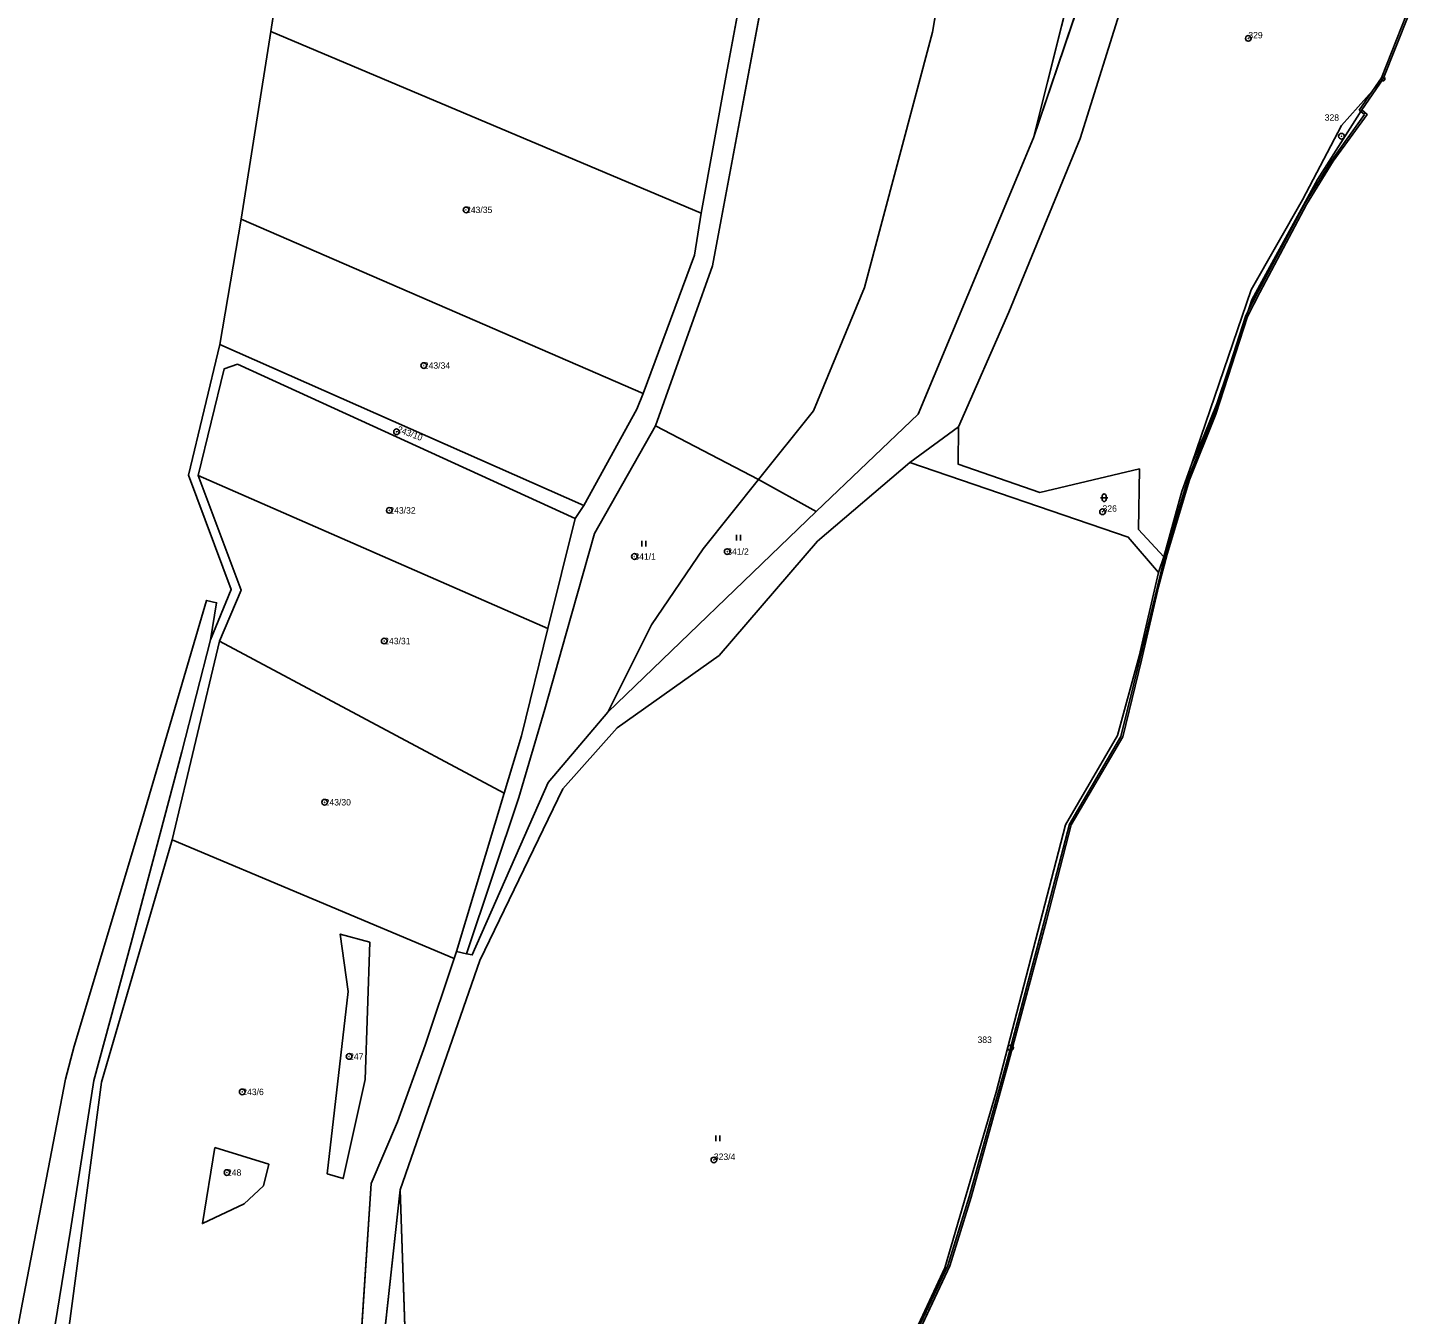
# Model space of a CAD drawing. Extents: x -652854 to -650068, y -1097661 to -1095417.
# Drawn here: x -650849.8 to -650484.7, y -1096839 to -1096498.9 of the extents above; entities that cross this region are included whole.
import ezdxf

# ---------------------------------------------------------------- set-up
doc = ezdxf.new("R2010")
doc.units = 0
for name, color, linetype in [('Definiční body parcel', 7, 'Continuous'), ('Geodetické body', 7, 'Continuous'), ('Hranice kat_ území', 7, 'Continuous'), ('Hranice parcel', 7, 'Continuous'), ('Obvody jako plochy', 7, 'Continuous'), ('Ostatní hranice', 7, 'Continuous'), ('Parcelní čísla', 7, 'Continuous'), ('Prvky pro prodl_ par_ č_', 7, 'Continuous'), ('Značky kultur', 7, 'Continuous')]:
    doc.layers.add(name, color=color, linetype=linetype)

msp = doc.modelspace()

# ---------------------------------------------------------------- linework, layer by layer
at = {"layer": 'Definiční body parcel'}
for centre, radius in [((-650526.99, -1096501.73), 0.75), ((-650526.99, -1096501.73), 0.0327), ((-650502.35, -1096527.6), 0.75), ((-650502.35, -1096527.6), 0.0327), ((-650733.87, -1096547.05), 0.75), ((-650733.87, -1096547.05), 0.0327), ((-650745.04, -1096588.2), 0.75), ((-650745.04, -1096588.2), 0.0327), ((-650752.26, -1096605.71), 0.75), ((-650752.26, -1096605.71), 0.0327), ((-650754.16, -1096626.49), 0.75), ((-650754.16, -1096626.49), 0.0327), ((-650565.55, -1096626.85), 0.75), ((-650565.55, -1096626.85), 0.0327), ((-650664.79, -1096637.39), 0.75), ((-650664.79, -1096637.39), 0.0327), ((-650689.35, -1096638.68), 0.75), ((-650689.35, -1096638.68), 0.0327), ((-650755.52, -1096661.03), 0.75), ((-650755.52, -1096661.03), 0.0327), ((-650771.27, -1096703.64), 0.75), ((-650771.27, -1096703.64), 0.0327), ((-650589.86, -1096768.59), 0.75), ((-650589.86, -1096768.59), 0.0327), ((-650764.8, -1096770.84), 0.75), ((-650764.8, -1096770.84), 0.0327), ((-650793.05, -1096780.2), 0.75), ((-650793.05, -1096780.2), 0.0327), ((-650668.33, -1096798.19), 0.75), ((-650668.33, -1096798.19), 0.0327), ((-650797.1, -1096801.52), 0.75), ((-650797.1, -1096801.52), 0.0327)]:
    msp.add_circle(centre, radius, dxfattribs=at)
at = {"layer": 'Geodetické body'}
for radius in [0.5, 0.001]:
    msp.add_circle((-650491.37, -1096512.46), radius, dxfattribs=at)
at = {"layer": 'Hranice kat_ území'}
for p, q in [((-650484.66, -1096495.59), (-650491.37, -1096512.46)), ((-650491.37, -1096512.46), (-650496.97, -1096520.6)), ((-650496.97, -1096520.6), (-650495.58, -1096521.81)), ((-650495.58, -1096521.81), (-650504.51, -1096534.18)), ((-650504.51, -1096534.18), (-650511.64, -1096545.63)), ((-650511.64, -1096545.63), (-650523.96, -1096568.9)), ((-650523.96, -1096568.9), (-650527.17, -1096575.2)), ((-650527.17, -1096575.2), (-650535.56, -1096601.1)), ((-650535.56, -1096601.1), (-650542.51, -1096618.41)), ((-650542.51, -1096618.41), (-650548.42, -1096638.04)), ((-650548.42, -1096638.04), (-650550.78, -1096646.66)), ((-650550.78, -1096646.66), (-650555.22, -1096666.07)), ((-650555.22, -1096666.07), (-650560.2, -1096686.39)), ((-650560.2, -1096686.39), (-650573.84, -1096709.65)), ((-650573.84, -1096709.65), (-650580.35, -1096734.9)), ((-650580.35, -1096734.9), (-650590.56, -1096773.04)), ((-650590.56, -1096773.04), (-650600.33, -1096808.06)), ((-650600.33, -1096808.06), (-650605.92, -1096826.18)), ((-650605.92, -1096826.18), (-650620.6, -1096857.32))]:
    msp.add_line(p, q, dxfattribs=at)
at = {"layer": 'Hranice parcel'}
for p, q in [((-650785.54, -1096499.95), (-650773.41, -1096422.59)), ((-650598.36, -1096429.24), (-650610.51, -1096500.05)), ((-650652.9, -1096477.63), (-650668.72, -1096561.85)), ((-650658.91, -1096478.22), (-650664.97, -1096511.01)), ((-650572.68, -1096483.75), (-650583.78, -1096528.02)), ((-650583.78, -1096528.02), (-650569.29, -1096485.13)), ((-650559.7, -1096490.72), (-650571.47, -1096528.21)), ((-650793.31, -1096549.53), (-650785.54, -1096499.95)), ((-650785.54, -1096499.95), (-650671.73, -1096547.95)), ((-650610.51, -1096500.05), (-650628.48, -1096567.58)), ((-650664.97, -1096511.01), (-650671.73, -1096547.95)), ((-650491.37, -1096512.46), (-650502.32, -1096524.73)), ((-650508.68, -1096539.04), (-650496.97, -1096520.6)), ((-650502.32, -1096524.73), (-650512.64, -1096544.42)), ((-650614.31, -1096601.07), (-650583.78, -1096528.02)), ((-650571.47, -1096528.21), (-650590.36, -1096574.12)), ((-650511.9, -1096544.81), (-650508.68, -1096539.04)), ((-650512.64, -1096544.42), (-650526.23, -1096568.21)), ((-650526.06, -1096570.86), (-650511.9, -1096544.81)), ((-650798.99, -1096582.65), (-650793.31, -1096549.53)), ((-650793.31, -1096549.53), (-650687.01, -1096595.59)), ((-650671.73, -1096547.95), (-650673.43, -1096559)), ((-650673.43, -1096559), (-650687.01, -1096595.59)), ((-650668.72, -1096561.85), (-650683.81, -1096604.11)), ((-650628.48, -1096567.58), (-650641.96, -1096600.14)), ((-650526.23, -1096568.21), (-650541.95, -1096614.11)), ((-650535.28, -1096598.37), (-650526.06, -1096570.86)), ((-650590.36, -1096574.12), (-650603.62, -1096604.37)), ((-650807.31, -1096617.17), (-650798.99, -1096582.65)), ((-650702.71, -1096625.17), (-650798.99, -1096582.65)), ((-650797.8, -1096589.04), (-650804.72, -1096617.23)), ((-650794.34, -1096587.83), (-650797.8, -1096589.04)), ((-650705.03, -1096628.63), (-650794.34, -1096587.83)), ((-650687.01, -1096595.59), (-650688.71, -1096599.72)), ((-650688.71, -1096599.72), (-650702.71, -1096625.17)), ((-650641.96, -1096600.14), (-650656.55, -1096618.34)), ((-650538.65, -1096606.62), (-650535.28, -1096598.37)), ((-650683.81, -1096604.11), (-650699.9, -1096632.64)), ((-650656.55, -1096618.34), (-650683.81, -1096604.11)), ((-650614.31, -1096601.07), (-650641.3, -1096626.82)), ((-650603.62, -1096604.37), (-650616.47, -1096613.8)), ((-650603.69, -1096614.28), (-650603.62, -1096604.37)), ((-650541.95, -1096614.11), (-650538.65, -1096606.62)), ((-650616.47, -1096613.8), (-650640.95, -1096634.64)), ((-650616.47, -1096613.8), (-650558.74, -1096633.54)), ((-650582.16, -1096621.77), (-650603.69, -1096614.28)), ((-650555.81, -1096615.55), (-650582.16, -1096621.77)), ((-650556, -1096631.51), (-650555.81, -1096615.55)), ((-650541.95, -1096614.11), (-650544.57, -1096621.47)), ((-650795.97, -1096647.36), (-650807.31, -1096617.17)), ((-650804.72, -1096617.23), (-650793.38, -1096647.55)), ((-650804.72, -1096617.23), (-650712.28, -1096657.74)), ((-650656.55, -1096618.34), (-650671.15, -1096636.66)), ((-650641.3, -1096626.82), (-650656.55, -1096618.34)), ((-650544.57, -1096621.47), (-650549.36, -1096638.74)), ((-650702.71, -1096625.17), (-650705.03, -1096628.63)), ((-650705.03, -1096628.63), (-650712.28, -1096657.74)), ((-650696.37, -1096679.84), (-650641.3, -1096626.82)), ((-650699.9, -1096632.64), (-650707.4, -1096659)), ((-650558.74, -1096633.54), (-650550.76, -1096642.89)), ((-650549.36, -1096638.74), (-650556, -1096631.51)), ((-650671.15, -1096636.66), (-650684.79, -1096656.72)), ((-650640.95, -1096634.64), (-650666.97, -1096664.83)), ((-650550.76, -1096642.89), (-650549.36, -1096638.74)), ((-650550.76, -1096642.89), (-650555.85, -1096665.06)), ((-650801.47, -1096660.7), (-650795.97, -1096647.36)), ((-650799.05, -1096661.1), (-650793.38, -1096647.55)), ((-650802.47, -1096650.3), (-650819.95, -1096709.68)), ((-650799.85, -1096650.9), (-650802.47, -1096650.3)), ((-650801.47, -1096660.7), (-650799.85, -1096650.9)), ((-650712.28, -1096657.74), (-650719.22, -1096686.09)), ((-650707.4, -1096659), (-650713.04, -1096679)), ((-650684.79, -1096656.72), (-650696.37, -1096679.84)), ((-650811.59, -1096713.59), (-650799.05, -1096661.1)), ((-650809.04, -1096690.29), (-650801.47, -1096660.7)), ((-650799.05, -1096661.1), (-650723.79, -1096701.28)), ((-650666.97, -1096664.83), (-650693.87, -1096683.97)), ((-650555.85, -1096665.06), (-650561.55, -1096686.01)), ((-650713.04, -1096679), (-650719.9, -1096702.42)), ((-650712.12, -1096698.4), (-650696.37, -1096679.84)), ((-650693.87, -1096683.97), (-650708.27, -1096700.08)), ((-650719.22, -1096686.09), (-650723.79, -1096701.28)), ((-650561.55, -1096686.01), (-650575.38, -1096709.57)), ((-650822.45, -1096740.82), (-650809.04, -1096690.29)), ((-650732.22, -1096743.98), (-650712.12, -1096698.4)), ((-650723.79, -1096701.28), (-650736.37, -1096743.07)), ((-650719.9, -1096702.42), (-650733.72, -1096743.7)), ((-650708.27, -1096700.08), (-650730.26, -1096745.43)), ((-650819.95, -1096709.68), (-650837.51, -1096768.15)), ((-650575.38, -1096709.57), (-650593.68, -1096780.27)), ((-650830.29, -1096777.64), (-650811.59, -1096713.59)), ((-650737, -1096744.96), (-650811.59, -1096713.59)), ((-650759.32, -1096740.66), (-650767.12, -1096738.47)), ((-650767.12, -1096738.47), (-650765.09, -1096753.67)), ((-650832.35, -1096777.19), (-650822.45, -1096740.82)), ((-650760.55, -1096776.92), (-650759.32, -1096740.66)), ((-650736.37, -1096743.07), (-650737, -1096744.96)), ((-650736.37, -1096743.07), (-650733.72, -1096743.7)), ((-650730.26, -1096745.43), (-650751.3, -1096806.09)), ((-650737, -1096744.96), (-650744.66, -1096767.85)), ((-650733.72, -1096743.7), (-650732.22, -1096743.98)), ((-650765.09, -1096753.67), (-650770.62, -1096801.88)), ((-650837.51, -1096768.15), (-650839.76, -1096776.84)), ((-650744.66, -1096767.85), (-650752, -1096788.15)), ((-650839.76, -1096776.84), (-650851.23, -1096836.35)), ((-650838.97, -1096843.48), (-650830.29, -1096777.64)), ((-650838.52, -1096816.73), (-650832.35, -1096777.19)), ((-650766.33, -1096803.11), (-650760.55, -1096776.92)), ((-650593.68, -1096780.27), (-650607.29, -1096826.73)), ((-650752, -1096788.15), (-650758.96, -1096804.4)), ((-650800.3, -1096794.9), (-650803.58, -1096815)), ((-650786.07, -1096799.32), (-650800.3, -1096794.9)), ((-650787.47, -1096805.01), (-650786.07, -1096799.32)), ((-650792.55, -1096809.79), (-650787.47, -1096805.01)), ((-650770.62, -1096801.88), (-650766.33, -1096803.11)), ((-650758.96, -1096804.4), (-650762.71, -1096861.22)), ((-650751.3, -1096806.09), (-650757.77, -1096864.86)), ((-650749.78, -1096850.04), (-650751.3, -1096806.09)), ((-650803.58, -1096815), (-650792.55, -1096809.79)), ((-650842.5, -1096841.66), (-650838.52, -1096816.73)), ((-650607.29, -1096826.73), (-650631.79, -1096879.39))]:
    msp.add_line(p, q, dxfattribs=at)
at = {"layer": 'Obvody jako plochy'}
for points in [[(-650615.39, -1096224.69), (-650627.74, -1096265.94), (-650633.03, -1096284.37), (-650678.51, -1096272.34), (-650676.87, -1096343.5), (-650663.97, -1096403.54), (-650652.67, -1096447.91), (-650652.9, -1096477.63), (-650668.72, -1096561.85), (-650683.81, -1096604.11), (-650656.55, -1096618.34), (-650641.96, -1096600.14), (-650628.48, -1096567.58), (-650610.51, -1096500.05), (-650598.36, -1096429.24), (-650603.36, -1096390.83), (-650603.97, -1096349.81), (-650597.72, -1096321.86), (-650593.22, -1096283.03), (-650569.84, -1096224.92), (-650587.51, -1096217.28), (-650610.66, -1096208.54)], [(-650799.85, -1096650.9), (-650801.47, -1096660.7), (-650795.97, -1096647.36), (-650807.31, -1096617.17), (-650798.99, -1096582.65), (-650793.31, -1096549.53), (-650785.54, -1096499.95), (-650773.41, -1096422.59), (-650773.25, -1096394.71), (-650771.95, -1096365.02), (-650824.93, -1096315.79), (-650882.2, -1096467.08), (-650940.33, -1096616.41), (-650895.72, -1096750.97), (-650857.12, -1096867.39), (-650851.23, -1096836.35), (-650839.76, -1096776.84), (-650837.51, -1096768.15), (-650819.95, -1096709.68), (-650802.47, -1096650.3)], [(-650664.97, -1096511.01), (-650658.91, -1096478.22), (-650660.51, -1096466.72), (-650666.75, -1096464.34), (-650666.17, -1096468.53), (-650755.6, -1096430.5), (-650773.41, -1096422.59), (-650785.54, -1096499.95), (-650671.73, -1096547.95)], [(-650583.78, -1096528.02), (-650569.29, -1096485.13), (-650547.69, -1096433.97), (-650551.98, -1096432.97), (-650572.68, -1096483.75)], [(-650673.43, -1096559), (-650671.73, -1096547.95), (-650785.54, -1096499.95), (-650793.31, -1096549.53), (-650687.01, -1096595.59)], [(-650541.95, -1096614.11), (-650538.65, -1096606.62), (-650535.28, -1096598.37), (-650526.06, -1096570.86), (-650511.9, -1096544.81), (-650508.68, -1096539.04), (-650496.97, -1096520.6), (-650491.37, -1096512.46), (-650502.32, -1096524.73), (-650512.64, -1096544.42), (-650526.23, -1096568.21)], [(-650688.71, -1096599.72), (-650687.01, -1096595.59), (-650793.31, -1096549.53), (-650798.99, -1096582.65), (-650702.71, -1096625.17)], [(-650794.34, -1096587.83), (-650705.03, -1096628.63), (-650702.71, -1096625.17), (-650798.99, -1096582.65), (-650807.31, -1096617.17), (-650795.97, -1096647.36), (-650801.47, -1096660.7), (-650809.04, -1096690.29), (-650822.45, -1096740.82), (-650832.35, -1096777.19), (-650838.52, -1096816.73), (-650842.5, -1096841.66), (-650838.97, -1096843.48), (-650830.29, -1096777.64), (-650811.59, -1096713.59), (-650799.05, -1096661.1), (-650793.38, -1096647.55), (-650804.72, -1096617.23), (-650797.8, -1096589.04)], [(-650794.34, -1096587.83), (-650797.8, -1096589.04), (-650804.72, -1096617.23), (-650712.28, -1096657.74), (-650705.03, -1096628.63)], [(-650732.22, -1096743.98), (-650712.12, -1096698.4), (-650696.37, -1096679.84), (-650684.79, -1096656.72), (-650671.15, -1096636.66), (-650656.55, -1096618.34), (-650683.81, -1096604.11), (-650699.9, -1096632.64), (-650707.4, -1096659), (-650713.04, -1096679), (-650719.9, -1096702.42), (-650733.72, -1096743.7)], [(-650556, -1096631.51), (-650555.81, -1096615.55), (-650582.16, -1096621.77), (-650603.69, -1096614.28), (-650603.62, -1096604.37), (-650616.47, -1096613.8), (-650558.74, -1096633.54), (-650550.76, -1096642.89), (-650549.36, -1096638.74)], [(-650640.95, -1096634.64), (-650666.97, -1096664.83), (-650693.87, -1096683.97), (-650708.27, -1096700.08), (-650730.26, -1096745.43), (-650751.3, -1096806.09), (-650749.78, -1096850.04), (-650749.24, -1096861.26), (-650718.61, -1096874.57), (-650732.62, -1096946.61), (-650664.55, -1096963.78), (-650656.85, -1096941.5), (-650642.07, -1096907.01), (-650631.79, -1096879.39), (-650607.29, -1096826.73), (-650593.68, -1096780.27), (-650575.38, -1096709.57), (-650561.55, -1096686.01), (-650555.85, -1096665.06), (-650550.76, -1096642.89), (-650558.74, -1096633.54), (-650616.47, -1096613.8)], [(-650719.22, -1096686.09), (-650712.28, -1096657.74), (-650804.72, -1096617.23), (-650793.38, -1096647.55), (-650799.05, -1096661.1), (-650723.79, -1096701.28)], [(-650696.37, -1096679.84), (-650641.3, -1096626.82), (-650656.55, -1096618.34), (-650671.15, -1096636.66), (-650684.79, -1096656.72)], [(-650811.59, -1096713.59), (-650737, -1096744.96), (-650736.37, -1096743.07), (-650723.79, -1096701.28), (-650799.05, -1096661.1)], [(-650744.66, -1096767.85), (-650737, -1096744.96), (-650811.59, -1096713.59), (-650830.29, -1096777.64), (-650838.97, -1096843.48), (-650762.99, -1096887.62), (-650762.71, -1096861.22), (-650758.96, -1096804.4), (-650752, -1096788.15)], [(-650770.62, -1096801.88), (-650765.09, -1096753.67), (-650767.12, -1096738.47), (-650759.32, -1096740.66), (-650760.55, -1096776.92), (-650766.33, -1096803.11)], [(-650770.62, -1096801.88), (-650766.33, -1096803.11), (-650760.55, -1096776.92), (-650759.32, -1096740.66), (-650767.12, -1096738.47), (-650765.09, -1096753.67)], [(-650800.3, -1096794.9), (-650786.07, -1096799.32), (-650787.47, -1096805.01), (-650792.55, -1096809.79), (-650803.58, -1096815)], [(-650800.3, -1096794.9), (-650803.58, -1096815), (-650792.55, -1096809.79), (-650787.47, -1096805.01), (-650786.07, -1096799.32)], [(-650757.77, -1096864.86), (-650752.97, -1096938.98), (-650764.28, -1097007.66), (-650770.63, -1097044.8), (-650770.8, -1097108.22), (-650768.15, -1097111.11), (-650764.71, -1097065.35), (-650768.35, -1097045.09), (-650743.39, -1097063.35), (-650730.12, -1097020.9), (-650728.16, -1097014.62), (-650733.21, -1097000.77), (-650742.25, -1097001.77), (-650752.26, -1097002.72), (-650746.22, -1096970.65), (-650746.25, -1096938.19), (-650749.24, -1096861.26), (-650749.78, -1096850.04), (-650751.3, -1096806.09)]]:
    msp.add_lwpolyline(points, close=True, dxfattribs=at)
for points in [[(-650598.36, -1096429.24), (-650610.51, -1096500.05), (-650628.48, -1096567.58), (-650641.96, -1096600.14), (-650656.55, -1096618.34), (-650641.3, -1096626.82), (-650614.31, -1096601.07), (-650583.78, -1096528.02), (-650572.68, -1096483.75)], [(-650658.91, -1096478.22), (-650664.97, -1096511.01), (-650671.73, -1096547.95), (-650673.43, -1096559), (-650687.01, -1096595.59), (-650688.71, -1096599.72), (-650702.71, -1096625.17), (-650705.03, -1096628.63), (-650712.28, -1096657.74), (-650719.22, -1096686.09), (-650723.79, -1096701.28), (-650736.37, -1096743.07), (-650733.72, -1096743.7), (-650719.9, -1096702.42), (-650713.04, -1096679), (-650707.4, -1096659), (-650699.9, -1096632.64), (-650683.81, -1096604.11), (-650668.72, -1096561.85), (-650652.9, -1096477.63)], [(-650569.29, -1096485.13), (-650583.78, -1096528.02), (-650614.31, -1096601.07), (-650641.3, -1096626.82), (-650696.37, -1096679.84), (-650712.12, -1096698.4), (-650732.22, -1096743.98), (-650733.72, -1096743.7), (-650736.37, -1096743.07), (-650737, -1096744.96), (-650744.66, -1096767.85), (-650752, -1096788.15), (-650758.96, -1096804.4), (-650762.71, -1096861.22), (-650761.31, -1096861.98), (-650756.21, -1096938.67), (-650768.43, -1097007.3), (-650775.22, -1097043.42), (-650773.96, -1097109.54)], [(-650770.8, -1097108.22), (-650770.63, -1097044.8), (-650764.28, -1097007.66), (-650752.97, -1096938.98), (-650757.77, -1096864.86), (-650751.3, -1096806.09), (-650730.26, -1096745.43), (-650708.27, -1096700.08), (-650693.87, -1096683.97), (-650666.97, -1096664.83), (-650640.95, -1096634.64), (-650616.47, -1096613.8), (-650603.62, -1096604.37), (-650590.36, -1096574.12), (-650571.47, -1096528.21), (-650559.7, -1096490.72)], [(-650559.7, -1096490.72), (-650571.47, -1096528.21), (-650590.36, -1096574.12), (-650603.62, -1096604.37), (-650603.69, -1096614.28), (-650582.16, -1096621.77), (-650555.81, -1096615.55), (-650556, -1096631.51), (-650549.36, -1096638.74), (-650544.57, -1096621.47), (-650541.95, -1096614.11), (-650526.23, -1096568.21), (-650512.64, -1096544.42), (-650502.32, -1096524.73), (-650491.37, -1096512.46), (-650484.66, -1096495.59)], [(-650620.6, -1096857.32), (-650605.92, -1096826.18), (-650600.33, -1096808.06), (-650590.56, -1096773.04), (-650580.35, -1096734.9), (-650573.84, -1096709.65), (-650560.2, -1096686.39), (-650555.22, -1096666.07), (-650550.78, -1096646.66), (-650548.42, -1096638.04), (-650542.51, -1096618.41), (-650535.56, -1096601.1), (-650527.17, -1096575.2), (-650523.96, -1096568.9), (-650511.64, -1096545.63), (-650504.51, -1096534.18), (-650495.58, -1096521.81), (-650496.97, -1096520.6), (-650508.68, -1096539.04), (-650511.9, -1096544.81), (-650526.06, -1096570.86), (-650535.28, -1096598.37), (-650538.65, -1096606.62), (-650541.95, -1096614.11), (-650544.57, -1096621.47), (-650549.36, -1096638.74), (-650550.76, -1096642.89), (-650555.85, -1096665.06), (-650561.55, -1096686.01), (-650575.38, -1096709.57), (-650593.68, -1096780.27), (-650607.29, -1096826.73), (-650631.79, -1096879.39)], [(-650855.98, -1096907.12), (-650848.06, -1096877.3), (-650848.73, -1096876.93), (-650842.5, -1096841.66), (-650838.52, -1096816.73), (-650832.35, -1096777.19), (-650822.45, -1096740.82), (-650809.04, -1096690.29), (-650801.47, -1096660.7), (-650799.85, -1096650.9), (-650802.47, -1096650.3), (-650819.95, -1096709.68), (-650837.51, -1096768.15), (-650839.76, -1096776.84), (-650851.23, -1096836.35)]]:
    msp.add_lwpolyline(points, dxfattribs=at)
at = {"layer": 'Ostatní hranice'}
for p, q in [((-650485.15, -1096495.42), (-650491.8, -1096512.19)), ((-650491.8, -1096512.19), (-650497.64, -1096520.69)), ((-650497.64, -1096520.69), (-650496.26, -1096521.89)), ((-650496.26, -1096521.89), (-650504.94, -1096533.91)), ((-650504.94, -1096533.91), (-650512.08, -1096545.38)), ((-650512.08, -1096545.38), (-650524.4, -1096568.64)), ((-650524.4, -1096568.64), (-650527.61, -1096574.95)), ((-650527.61, -1096574.95), (-650536.04, -1096600.94)), ((-650536.04, -1096600.94), (-650543, -1096618.26)), ((-650543, -1096618.26), (-650548.92, -1096637.93)), ((-650548.92, -1096637.93), (-650555.71, -1096665.94)), ((-650555.71, -1096665.94), (-650560.68, -1096686.22)), ((-650560.68, -1096686.22), (-650574.31, -1096709.46)), ((-650574.31, -1096709.46), (-650580.85, -1096734.79)), ((-650580.85, -1096734.79), (-650591.05, -1096772.91)), ((-650591.05, -1096772.91), (-650600.82, -1096807.92)), ((-650600.82, -1096807.92), (-650606.42, -1096826.06)), ((-650606.42, -1096826.06), (-650621.05, -1096857.07))]:
    msp.add_line(p, q, dxfattribs=at)
at = {"layer": 'Značky kultur'}
for p, q in [((-650565.62, -1096623.65), (-650565.62, -1096622.65)), ((-650564.62, -1096623.65), (-650564.62, -1096622.65)), ((-650566.12, -1096623.15), (-650564.12, -1096623.15)), ((-650662.337, -1096632.955), (-650662.337, -1096634.455)), ((-650661.315, -1096634.455), (-650661.315, -1096632.955)), ((-650687.367, -1096634.565), (-650687.367, -1096636.065)), ((-650686.345, -1096636.065), (-650686.345, -1096634.565)), ((-650667.797, -1096791.745), (-650667.797, -1096793.245)), ((-650666.775, -1096793.245), (-650666.775, -1096791.745))]:
    msp.add_line(p, q, dxfattribs=at)
for centre, start, end in [((-650565.12, -1096622.65), 0, 180), ((-650565.12, -1096623.65), 180, 0)]:
    msp.add_arc(centre, 0.5, start, end, dxfattribs=at)

# ---------------------------------------------------------------- texts
at = {"layer": 'Parcelní čísla'}
for s, height, p in [('329', 1.7, (-650526.99, -1096501.73)), ('328', 0.1, (-650502.35, -1096527.6)), ('243/35', 1.7, (-650733.87, -1096547.9)), ('243/34', 1.7, (-650745.04, -1096589.05)), ('243/32', 1.7, (-650754.16, -1096627.34)), ('326', 1.7, (-650565.55, -1096626.85)), ('341/2', 1.7, (-650664.79, -1096638.24)), ('341/1', 1.7, (-650689.35, -1096639.53)), ('243/31', 1.7, (-650755.52, -1096661.88)), ('243/30', 1.7, (-650771.27, -1096704.49)), ('383', 0.1, (-650589.86, -1096768.59)), ('247', 1.7, (-650764.8, -1096771.69)), ('243/6', 1.7, (-650793.05, -1096781.05)), ('323/4', 1.7, (-650668.33, -1096798.19)), ('248', 1.7, (-650797.1, -1096802.37))]:
    msp.add_text(s, height=height, dxfattribs=at).set_placement(p)
msp.add_text('243/10', height=1.7, rotation=339.3, dxfattribs=at).set_placement((-650752.26, -1096605.71))
at = {"layer": 'Prvky pro prodl_ par_ č_'}
for s, p in [('328', (-650506.79, -1096523.5)), ('383', (-650598.61, -1096767.26))]:
    msp.add_text(s, height=1.7, dxfattribs=at).set_placement(p)

doc.saveas('drawing.dxf')
